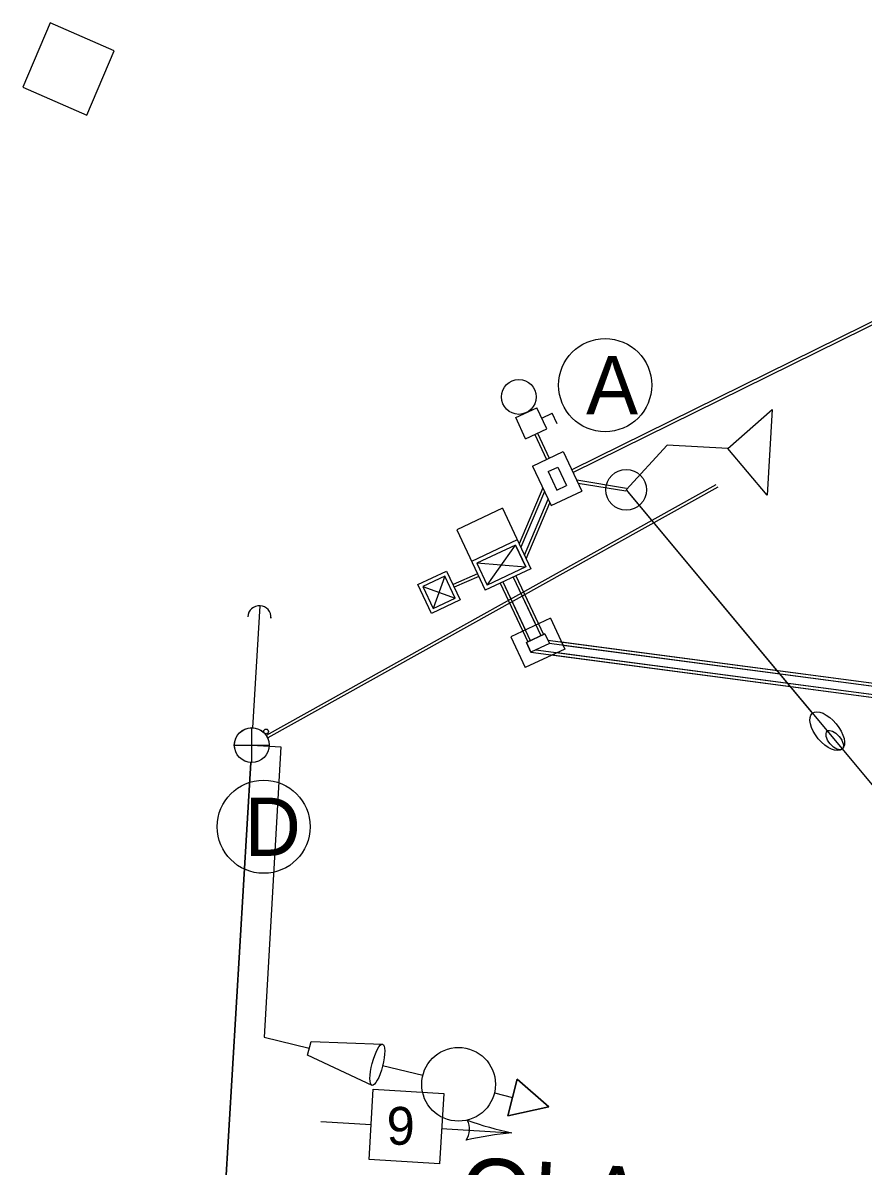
# Model space of a CAD drawing. Extents: x 647787 to 668496, y 640478 to 654412.
# Drawn here: x 661717.7 to 661789.9, y 647356.9 to 647455.1 of the extents above; entities that cross this region are included whole.
import ezdxf

# ---------------------------------------------------------------- set-up
doc = ezdxf.new("R2010")
doc.units = 0
for name, color, linetype in [('Default', 7, 'Continuous'), ('TEMP_DETECTION ZONE_Stage 2', 7, 'Continuous'), ('TEMP_SIGNAL POLES', 7, 'Continuous'), ('TEMP_SIGNAL_CONDUIT_1', 7, 'Continuous'), ('TEMP_SIGNAL_HEAD_STAGE 1A', 7, 'Continuous'), ('TEMP_SIGNAL_HEAD_STAGE 2', 7, 'Continuous'), ('TEMP_SIGNAL_HEAD_STAGE 3 SHILO', 7, 'Continuous'), ('TEMP_SIGNAL_HEAD_STAGE 4 SHILO', 7, 'Continuous'), ('TEMP_SIGNAL_POLES_STAGE 1A', 7, 'Continuous'), ('TEMP_SIGNAL_POLES_STAGE 2', 7, 'Continuous'), ('TEMP_SIGNAL_POLES_STAGE 3', 7, 'Continuous'), ('TEMP_SIGNAL_POLES_STAGE 3-1', 7, 'Continuous'), ('TEMP_SIGNAL_POLES_STAGE 4', 7, 'Continuous'), ('TEMP_SIGNAL_POLES_STAGE 5', 7, 'Continuous'), ('TEMP_SIGNAL_POLES_STAGES 3-4', 7, 'Continuous'), ('TEXT_TEMP_SIGNAL_POLES_STAGE 2', 7, 'Continuous'), ('TEXT_TEMP_SIGNAL_POLES_STAGE 3', 7, 'Continuous'), ('TEXT_TEMP_SIGNAL_POLES_STAGE 4', 7, 'Continuous'), ('TEXT_TEMP_SIGNAL_POLES_STAGE 5', 7, 'Continuous')]:
    doc.layers.add(name, color=color, linetype=linetype)

msp = doc.modelspace()

# ---------------------------------------------------------------- linework, layer by layer
at = {"layer": 'TEMP_DETECTION ZONE_Stage 2'}
for points in [[(661717.695, 647449.591), (661723.194, 647447.191), (661725.548, 647452.71), (661720.048, 647455.11)], [(661717.695, 647449.591), (661723.194, 647447.191), (661725.548, 647452.71), (661720.048, 647455.11)], [(661717.695, 647449.591), (661723.194, 647447.191), (661725.548, 647452.71), (661720.048, 647455.11)], [(661717.697, 647449.592), (661723.197, 647447.193), (661725.55, 647452.712), (661720.051, 647455.112)]]:
    msp.add_lwpolyline(points, close=True, dxfattribs=at)
at = {"layer": 'TEMP_SIGNAL POLES'}
for p, q in [((661737.362, 647391.535), (661737.362, 647394.535)), ((661737.362, 647391.535), (661737.362, 647394.535)), ((661737.362, 647391.535), (661737.362, 647394.535)), ((661737.364, 647391.537), (661737.364, 647394.537)), ((661735.862, 647393.035), (661738.862, 647393.035)), ((661735.862, 647393.035), (661738.862, 647393.035)), ((661735.862, 647393.035), (661738.862, 647393.035)), ((661735.864, 647393.037), (661738.864, 647393.037))]:
    msp.add_line(p, q, dxfattribs=at)
for centre, radius in [((661737.362, 647393.035), 1.5), ((661737.362, 647393.035), 1.5), ((661737.362, 647393.035), 1.5), ((661737.364, 647393.037), 1.5), ((661738.591, 647394.21), 0.2), ((661738.591, 647394.21), 0.2), ((661738.591, 647394.21), 0.2), ((661738.593, 647394.211), 0.2)]:
    msp.add_circle(centre, radius, dxfattribs=at)
at = {"layer": 'TEMP_SIGNAL_CONDUIT_1'}
for p, q in [((661777.236, 647415.403), (661738.606, 647393.872)), ((661777.236, 647415.403), (661738.606, 647393.872)), ((661777.399, 647415.208), (661738.728, 647393.654)), ((661777.399, 647415.208), (661738.728, 647393.654))]:
    msp.add_line(p, q, dxfattribs=at)
at = {"layer": 'TEMP_SIGNAL_HEAD_STAGE 1A'}
for p, q in [((661796.64, 647432.37), (661764.86, 647416.702)), ((661796.64, 647432.37), (661764.86, 647416.702)), ((661796.805, 647432.172), (661764.967, 647416.475)), ((661796.805, 647432.172), (661764.967, 647416.475)), ((661760.039, 647421.183), (661761.849, 647422.033)), ((661760.039, 647421.183), (661761.849, 647422.033)), ((661762.699, 647420.223), (661761.849, 647422.033)), ((661762.699, 647420.223), (661761.849, 647422.033)), ((661760.889, 647419.372), (661760.039, 647421.183)), ((661760.889, 647419.372), (661760.039, 647421.183)), ((661762.274, 647421.128), (661763.179, 647421.553)), ((661762.274, 647421.128), (661763.179, 647421.553)), ((661763.604, 647420.648), (661763.179, 647421.553)), ((661763.604, 647420.648), (661763.179, 647421.553)), ((661760.889, 647419.372), (661762.699, 647420.223)), ((661760.889, 647419.372), (661762.699, 647420.223)), ((661761.907, 647419.851), (661762.921, 647417.694)), ((661761.907, 647419.851), (661762.921, 647417.694)), ((661761.681, 647419.745), (661762.695, 647417.587)), ((661761.681, 647419.745), (661762.695, 647417.587)), ((661761.488, 647417.02), (661764.128, 647418.261)), ((661761.488, 647417.02), (661764.128, 647418.261)), ((661764.128, 647418.261), (661765.723, 647414.867)), ((661764.128, 647418.261), (661765.723, 647414.867)), ((661761.488, 647417.02), (661763.083, 647413.626)), ((661761.488, 647417.02), (661763.083, 647413.626)), ((661762.818, 647416.541), (661763.648, 647416.93)), ((661762.818, 647416.541), (661763.648, 647416.93)), ((661763.648, 647416.93), (661764.392, 647415.347)), ((661763.648, 647416.93), (661764.392, 647415.347)), ((661762.818, 647416.541), (661763.563, 647414.957)), ((661762.818, 647416.541), (661763.563, 647414.957)), ((661762.366, 647415.152), (661760.329, 647410.341)), ((661762.366, 647415.152), (661760.329, 647410.341)), ((661763.563, 647414.957), (661764.392, 647415.347)), ((661763.563, 647414.957), (661764.392, 647415.347)), ((661769.548, 647415.104), (661765.286, 647415.797)), ((661769.548, 647415.104), (661765.286, 647415.797)), ((661769.507, 647414.857), (661765.415, 647415.523)), ((661769.507, 647414.857), (661765.415, 647415.523)), ((661762.509, 647414.848), (661760.472, 647410.037)), ((661762.509, 647414.848), (661760.472, 647410.037)), ((661760.787, 647409.365), (661762.825, 647414.176)), ((661760.787, 647409.365), (661762.825, 647414.176)), ((661763.083, 647413.626), (661765.723, 647414.867)), ((661763.083, 647413.626), (661765.723, 647414.867)), ((661760.93, 647409.061), (661762.968, 647413.872)), ((661760.93, 647409.061), (661762.968, 647413.872)), ((661751.626, 647406.829), (661754.106, 647407.994)), ((661751.626, 647406.829), (661754.106, 647407.994)), ((661753.948, 647407.555), (661752.065, 647406.671)), ((661753.948, 647407.555), (661752.065, 647406.671)), ((661753.948, 647407.555), (661752.95, 647404.788)), ((661753.948, 647407.555), (661752.95, 647404.788)), ((661754.832, 647405.673), (661753.948, 647407.555)), ((661754.832, 647405.673), (661753.948, 647407.555)), ((661754.106, 647407.994), (661755.271, 647405.515)), ((661754.106, 647407.994), (661755.271, 647405.515)), ((661756.759, 647407.757), (661754.651, 647406.834)), ((661756.759, 647407.757), (661754.651, 647406.834)), ((661756.865, 647407.53), (661754.757, 647406.608)), ((661756.865, 647407.53), (661754.757, 647406.608)), ((661758.926, 647407.06), (661761.294, 647402.02)), ((661758.926, 647407.06), (661760.869, 647402.925)), ((661759.831, 647407.485), (661762.199, 647402.445)), ((661759.831, 647407.485), (661761.774, 647403.35)), ((661760.057, 647407.592), (661762.426, 647402.551)), ((661760.057, 647407.592), (661762, 647403.456)), ((661752.791, 647404.349), (661751.626, 647406.829)), ((661752.791, 647404.349), (661751.626, 647406.829)), ((661752.065, 647406.671), (661754.832, 647405.673)), ((661752.065, 647406.671), (661752.95, 647404.788)), ((661752.065, 647406.671), (661754.832, 647405.673)), ((661752.065, 647406.671), (661752.95, 647404.788)), ((661758.7, 647406.954), (661761.068, 647401.913)), ((661758.7, 647406.954), (661760.643, 647402.818)), ((661755.271, 647405.515), (661752.791, 647404.349)), ((661755.271, 647405.515), (661752.791, 647404.349)), ((661752.95, 647404.788), (661754.832, 647405.673)), ((661752.95, 647404.788), (661754.832, 647405.673)), ((661763.019, 647403.935), (661759.625, 647402.34)), ((661763.019, 647403.935), (661764.259, 647401.295)), ((661759.625, 647402.34), (661760.865, 647399.7)), ((661760.955, 647401.86), (661762.539, 647402.604)), ((661762.539, 647402.604), (661760.955, 647401.86)), ((661762.539, 647402.604), (661762.929, 647401.775)), ((661762.539, 647402.604), (661762.929, 647401.775)), ((661764.259, 647401.295), (661760.865, 647399.7)), ((661761.345, 647401.03), (661760.955, 647401.86)), ((661760.955, 647401.86), (661761.345, 647401.03)), ((661762.929, 647401.775), (661761.345, 647401.03)), ((661762.929, 647401.775), (661761.345, 647401.03)), ((661761.764, 647401.227), (661848.014, 647389.837)), ((661762.797, 647402.055), (661848.014, 647390.801)), ((661762.923, 647401.786), (661848.014, 647390.549)), ((661763.975, 647401.9), (661848.014, 647390.801)), ((661764.101, 647401.631), (661848.014, 647390.549)), ((661761.345, 647401.03), (661848.014, 647389.585)), ((661763.18, 647400.788), (661848.014, 647389.585)), ((661763.599, 647400.985), (661848.014, 647389.837))]:
    msp.add_line(p, q, dxfattribs=at)
msp.add_circle((661760.306, 647422.965), 1.5, dxfattribs=at)
msp.add_circle((661760.306, 647422.965), 1.5, dxfattribs=at)
at = {"layer": 'TEMP_SIGNAL_HEAD_STAGE 2'}
for p, q in [((661743.283, 647360.7), (661747.623, 647360.438)), ((661753.675, 647360.073), (661759.704, 647359.71))]:
    msp.add_line(p, q, dxfattribs=at)
msp.add_lwpolyline([(661747.44, 647357.412), (661747.805, 647363.465), (661753.857, 647363.1), (661753.492, 647357.047)], close=True, dxfattribs=at)
for centre, radius, start, end in [((661754.447, 647360.026), 1.629, 324.70052, 28.39516), ((661765.862, 647388.53), 29.472, 250.20141, 257.93952), ((661762.353, 647330.356), 29.472, 95.15616, 102.89427)]:
    msp.add_arc(centre, radius, start, end, dxfattribs=at)
at = {"layer": 'TEMP_SIGNAL_HEAD_STAGE 3 SHILO'}
for points in [[(661738.416, 647367.933), (661742.305, 647366.989)], [(661738.416, 647367.933), (661742.305, 647366.989)], [(661742.155, 647366.403), (661742.451, 647367.563)], [(661742.155, 647366.403), (661742.451, 647367.563)], [(661742.451, 647367.563), (661748.607, 647367.349)], [(661742.451, 647367.563), (661748.607, 647367.349)], [(661747.7, 647363.789), (661742.155, 647366.403)], [(661747.7, 647363.789), (661742.155, 647366.403)], [(661752.048, 647364.628), (661748.598, 647365.462)], [(661752.048, 647364.628), (661748.598, 647365.462)], [(661759.36, 647361.178), (661760.156, 647364.316), (661762.884, 647361.954), (661759.36, 647361.178)], [(661759.36, 647361.178), (661760.156, 647364.316), (661762.884, 647361.954), (661759.36, 647361.178)], [(661758.207, 647363.14), (661759.758, 647362.747)], [(661758.207, 647363.14), (661759.758, 647362.747)]]:
    msp.add_lwpolyline(points, dxfattribs=at)
msp.add_lwpolyline([(661762.884, 647361.954), (661760.156, 647364.316), (661759.36, 647361.178)], close=True, dxfattribs=at)
msp.add_lwpolyline([(661762.884, 647361.954), (661760.156, 647364.316), (661759.36, 647361.178)], close=True, dxfattribs=at)
msp.add_circle((661755.128, 647363.884), 3.168, dxfattribs=at)
msp.add_circle((661755.128, 647363.884), 3.168, dxfattribs=at)
msp.add_ellipse((661748.153, 647365.569), major_axis=(0.454, 1.78), ratio=0.249111, dxfattribs=at)
msp.add_ellipse((661748.153, 647365.569), major_axis=(0.454, 1.78), ratio=0.249111, dxfattribs=at)
at = {"layer": 'TEMP_SIGNAL_HEAD_STAGE 4 SHILO'}
for points in [[(661738.416, 647367.933), (661742.305, 647366.989)], [(661738.416, 647367.933), (661742.305, 647366.989)], [(661742.155, 647366.403), (661742.451, 647367.563)], [(661742.155, 647366.403), (661742.451, 647367.563)], [(661742.451, 647367.563), (661748.607, 647367.349)], [(661742.451, 647367.563), (661748.607, 647367.349)], [(661747.7, 647363.789), (661742.155, 647366.403)], [(661747.7, 647363.789), (661742.155, 647366.403)], [(661752.048, 647364.628), (661748.598, 647365.462)], [(661752.048, 647364.628), (661748.598, 647365.462)], [(661759.36, 647361.178), (661760.156, 647364.316), (661762.884, 647361.954), (661759.36, 647361.178)], [(661759.36, 647361.178), (661760.156, 647364.316), (661762.884, 647361.954), (661759.36, 647361.178)], [(661758.207, 647363.14), (661759.758, 647362.747)], [(661758.207, 647363.14), (661759.758, 647362.747)]]:
    msp.add_lwpolyline(points, dxfattribs=at)
msp.add_lwpolyline([(661762.884, 647361.954), (661760.156, 647364.316), (661759.36, 647361.178)], close=True, dxfattribs=at)
msp.add_lwpolyline([(661762.884, 647361.954), (661760.156, 647364.316), (661759.36, 647361.178)], close=True, dxfattribs=at)
msp.add_circle((661755.128, 647363.884), 3.168, dxfattribs=at)
msp.add_circle((661755.128, 647363.884), 3.168, dxfattribs=at)
msp.add_ellipse((661748.153, 647365.569), major_axis=(0.454, 1.78), ratio=0.249111, dxfattribs=at)
msp.add_ellipse((661748.153, 647365.569), major_axis=(0.454, 1.78), ratio=0.249111, dxfattribs=at)
at = {"layer": 'TEMP_SIGNAL_POLES_STAGE 1A'}
for p, q in [((661773.053, 647418.83), (661769.528, 647414.98)), ((661769.528, 647414.98), (661810.478, 647365.8)), ((661769.528, 647414.98), (661785.525, 647395.768))]:
    msp.add_line(p, q, dxfattribs=at)
msp.add_lwpolyline([(661778.264, 647418.516), (661782.075, 647421.893), (661781.63, 647414.527), (661778.264, 647418.516), (661773.053, 647418.83)], dxfattribs=at)
msp.add_circle((661769.528, 647414.98), 1.75, dxfattribs=at)
for centre, major_axis in [((661786.804, 647394.231), (1.28, -1.537)), ((661787.444, 647393.463), (-0.64, 0.768))]:
    msp.add_ellipse(centre, major_axis=major_axis, ratio=0.5, dxfattribs=at)
at = {"layer": 'TEMP_SIGNAL_POLES_STAGE 2'}
for p, q in [((661737.451, 647394.533), (661738.074, 647405.014)), ((661737.451, 647394.533), (661738.074, 647405.014)), ((661737.451, 647394.533), (661738.074, 647405.014)), ((661737.453, 647394.534), (661738.077, 647405.016)), ((661737.273, 647391.538), (661729.08, 647253.81)), ((661737.273, 647391.538), (661729.08, 647253.81)), ((661737.273, 647391.538), (661729.08, 647253.81)), ((661737.275, 647391.54), (661729.082, 647253.812))]:
    msp.add_line(p, q, dxfattribs=at)
for centre in [(661738.015, 647404.016), (661738.015, 647404.016), (661738.015, 647404.016), (661738.017, 647404.018)]:
    msp.add_arc(centre, 1, 356.59578, 176.59578, dxfattribs=at)
at = {"layer": 'TEMP_SIGNAL_POLES_STAGE 3'}
for p, q in [((661737.362, 647393.035), (661739.857, 647392.891)), ((661737.362, 647393.035), (661739.857, 647392.891)), ((661737.362, 647393.035), (661739.857, 647392.891)), ((661737.364, 647393.037), (661739.86, 647392.893))]:
    msp.add_line(p, q, dxfattribs=at)
at = {"layer": 'TEMP_SIGNAL_POLES_STAGE 3-1'}
msp.add_lwpolyline([(661739.857, 647392.891), (661738.416, 647367.933)], dxfattribs=at)
msp.add_lwpolyline([(661739.857, 647392.891), (661738.416, 647367.933)], dxfattribs=at)
at = {"layer": 'TEMP_SIGNAL_POLES_STAGE 4'}
for p, q in [((661737.362, 647393.035), (661739.857, 647392.891)), ((661737.362, 647393.035), (661739.857, 647392.891)), ((661737.362, 647393.035), (661739.857, 647392.891)), ((661737.364, 647393.037), (661739.86, 647392.893))]:
    msp.add_line(p, q, dxfattribs=at)
for points in [[(661739.857, 647392.891), (661738.416, 647367.933)], [(661739.857, 647392.891), (661738.416, 647367.933)], [(661739.857, 647392.891), (661738.416, 647367.933)], [(661739.86, 647392.893), (661738.419, 647367.934)]]:
    msp.add_lwpolyline(points, dxfattribs=at)
at = {"layer": 'TEMP_SIGNAL_POLES_STAGE 5'}
for q in [(661810.478, 647365.8), (661785.525, 647395.768)]:
    msp.add_line((661769.528, 647414.98), q, dxfattribs=at)
msp.add_circle((661769.528, 647414.98), 1.75, dxfattribs=at)
for centre, major_axis in [((661786.804, 647394.231), (1.28, -1.537)), ((661787.444, 647393.463), (-0.64, 0.768))]:
    msp.add_ellipse(centre, major_axis=major_axis, ratio=0.5, dxfattribs=at)
at = {"layer": 'TEMP_SIGNAL_POLES_STAGES 3-4'}
for p, q in [((661737.451, 647394.533), (661738.074, 647405.014)), ((661737.451, 647394.533), (661738.074, 647405.014)), ((661729.08, 647253.81), (661737.273, 647391.538)), ((661729.08, 647253.81), (661737.273, 647391.538))]:
    msp.add_line(p, q, dxfattribs=at)
msp.add_arc((661738.015, 647404.016), 1, 356.59578, 176.59578, dxfattribs=at)
msp.add_arc((661738.015, 647404.016), 1, 356.59578, 176.59578, dxfattribs=at)
at = {"layer": 'TEXT_TEMP_SIGNAL_POLES_STAGE 2'}
msp.add_circle((661738.383, 647386.021), 4, dxfattribs=at)
at = {"layer": 'TEXT_TEMP_SIGNAL_POLES_STAGE 3'}
msp.add_circle((661738.383, 647386.021), 4, dxfattribs=at)
at = {"layer": 'TEXT_TEMP_SIGNAL_POLES_STAGE 4'}
msp.add_circle((661738.383, 647386.021), 4, dxfattribs=at)
at = {"layer": 'TEXT_TEMP_SIGNAL_POLES_STAGE 5'}
for p, q in [((661758.897, 647413.388), (661754.978, 647411.547)), ((661758.897, 647413.388), (661754.978, 647411.547)), ((661758.897, 647413.388), (661761.338, 647408.193)), ((661758.897, 647413.388), (661761.338, 647408.193)), ((661754.978, 647411.547), (661757.419, 647406.352)), ((661754.978, 647411.547), (661757.419, 647406.352)), ((661760.173, 647410.673), (661756.254, 647408.832)), ((661760.173, 647410.673), (661756.254, 647408.832)), ((661760.014, 647410.234), (661756.693, 647408.673)), ((661760.014, 647410.234), (661756.693, 647408.673)), ((661757.577, 647406.791), (661760.015, 647410.232)), ((661757.577, 647406.791), (661760.015, 647410.232)), ((661760.014, 647410.234), (661760.899, 647408.352)), ((661760.014, 647410.234), (661760.899, 647408.352)), ((661760.085, 647410.085), (661760.829, 647408.501)), ((661760.085, 647410.085), (661760.829, 647408.501)), ((661756.693, 647408.673), (661757.577, 647406.791)), ((661760.88, 647408.343), (661756.693, 647408.673)), ((661756.693, 647408.673), (661757.577, 647406.791)), ((661760.88, 647408.343), (661756.693, 647408.673)), ((661761.338, 647408.193), (661757.419, 647406.352)), ((661761.338, 647408.193), (661757.419, 647406.352)), ((661760.899, 647408.352), (661757.577, 647406.791)), ((661760.899, 647408.352), (661757.577, 647406.791))]:
    msp.add_line(p, q, dxfattribs=at)
msp.add_circle((661767.723, 647423.976), 4, dxfattribs=at)

# ---------------------------------------------------------------- texts
at = {"layer": 'Default'}
msp.add_text('OLA', height=6, rotation=356.61808, dxfattribs=at).set_placement((661755.066, 647351.662))
at = {"layer": 'TEXT_TEMP_SIGNAL_POLES_STAGE 2'}
for s, height, p in [('D', 5, (661736.749, 647383.521)), ('9', 3.25, (661748.948, 647358.692))]:
    msp.add_text(s, height=height, dxfattribs=at).set_placement(p)
at = {"layer": 'TEXT_TEMP_SIGNAL_POLES_STAGE 3'}
msp.add_text('D', height=5, dxfattribs=at).set_placement((661736.749, 647383.521))
at = {"layer": 'TEXT_TEMP_SIGNAL_POLES_STAGE 4'}
msp.add_text('D', height=5, dxfattribs=at).set_placement((661736.749, 647383.521))
at = {"layer": 'TEXT_TEMP_SIGNAL_POLES_STAGE 5'}
msp.add_text('A', height=5, dxfattribs=at).set_placement((661766.089, 647421.476))

doc.saveas('drawing.dxf')
